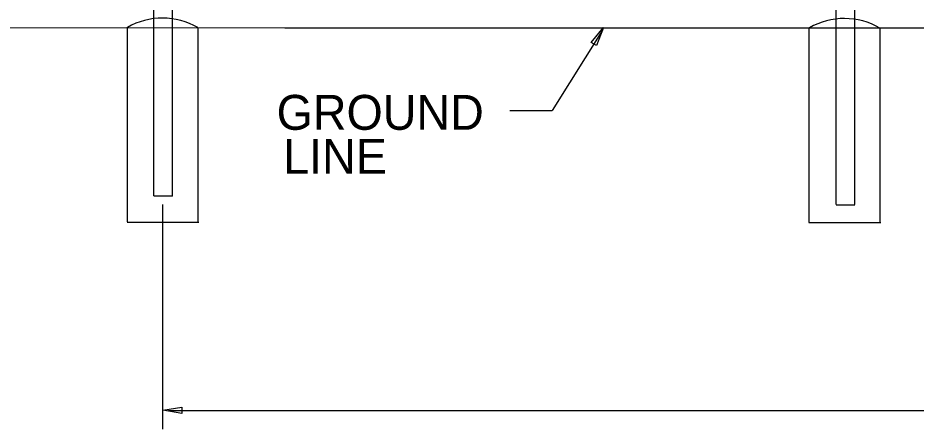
# Model space of a CAD drawing. Extents: x 0 to 2.85, y -0.1 to 1.83.
# Drawn here: x 1.0563 to 1.3139, y 0.6905 to 0.8084 of the extents above; entities that cross this region are included whole.
import ezdxf

# ---------------------------------------------------------------- set-up
doc = ezdxf.new("R2010")
doc.units = 0
for name, color, linetype in [('CT_Dimensions', 7, 'Continuous'), ('sb_Chainlink Fence', 7, 'Continuous'), ('sb_Existing Concrete', 7, 'Continuous'), ('sb_Existing Structural Steel', 7, 'Continuous')]:
    doc.layers.add(name, color=color, linetype=linetype)

msp = doc.modelspace()

# ---------------------------------------------------------------- linework, layer by layer
at = {"layer": 'CT_Dimensions'}
for p, q in [((1.19736, 0.78186), (1.20952, 0.78186)), ((1.0978, 0.69049), (1.0978, 0.75489)), ((1.09949, 0.6958), (1.87875, 0.6958))]:
    msp.add_line(p, q, dxfattribs=at)
msp.add_lwpolyline([(1.10329, 0.69494), (1.09779, 0.69586), (1.10329, 0.69678)], close=True, dxfattribs=at)
at = {"layer": 'sb_Chainlink Fence'}
for p, q in [((0.75445, 0.80587), (1.13401, 0.80557)), ((1.13283, 0.80557), (1.26429, 0.80554)), ((1.22389, 0.80483), (1.20952, 0.78186)), ((1.26139, 0.80554), (1.26429, 0.80554)), ((1.26429, 0.80554), (1.88005, 0.80558))]:
    msp.add_line(p, q, dxfattribs=at)
msp.add_lwpolyline([(1.22067, 0.80137), (1.22425, 0.80564), (1.22225, 0.80044)], close=True, dxfattribs=at)
at = {"layer": 'sb_Existing Concrete'}
for p, q in [((1.08765, 0.74995), (1.08765, 0.80576)), ((1.10793, 0.74972), (1.10793, 0.80553)), ((1.28321, 0.74974), (1.28321, 0.80555)), ((1.30359, 0.74973), (1.30359, 0.80554)), ((1.08761, 0.7498), (1.10812, 0.7498)), ((1.28311, 0.74974), (1.30374, 0.74973))]:
    msp.add_line(p, q, dxfattribs=at)
for centre in [(1.09769, 0.78804), (1.2933, 0.78792)]:
    msp.add_arc(centre, 0.02029, 59.953, 119.6876, dxfattribs=at)
at = {"layer": 'sb_Existing Structural Steel'}
for p, q in [((1.09525, 0.80565), (1.09525, 0.91525)), ((1.1006, 0.80558), (1.1006, 0.91535)), ((1.29092, 0.80764), (1.2909, 0.91558)), ((1.29629, 0.80748), (1.29623, 0.91582)), ((1.29092, 0.75483), (1.29092, 0.80764)), ((1.29629, 0.75486), (1.29629, 0.80748)), ((1.09525, 0.75732), (1.09525, 0.80565)), ((1.1006, 0.75725), (1.1006, 0.80558)), ((1.10057, 0.75731), (1.09525, 0.75731)), ((1.29093, 0.75479), (1.29631, 0.75479))]:
    msp.add_line(p, q, dxfattribs=at)

# ---------------------------------------------------------------- texts
at = {"layer": 'CT_Dimensions'}
for s, p in [('GROUND ', (1.13045, 0.7763)), ('LINE', (1.13235, 0.76368))]:
    msp.add_text(s, height=0.01, dxfattribs=at).set_placement(p)

doc.saveas('drawing.dxf')
